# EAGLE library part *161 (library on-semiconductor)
Universal Voltage Monitor Source: www.onsemi.com/pub_link/Collateral/MC34161-D.PDF
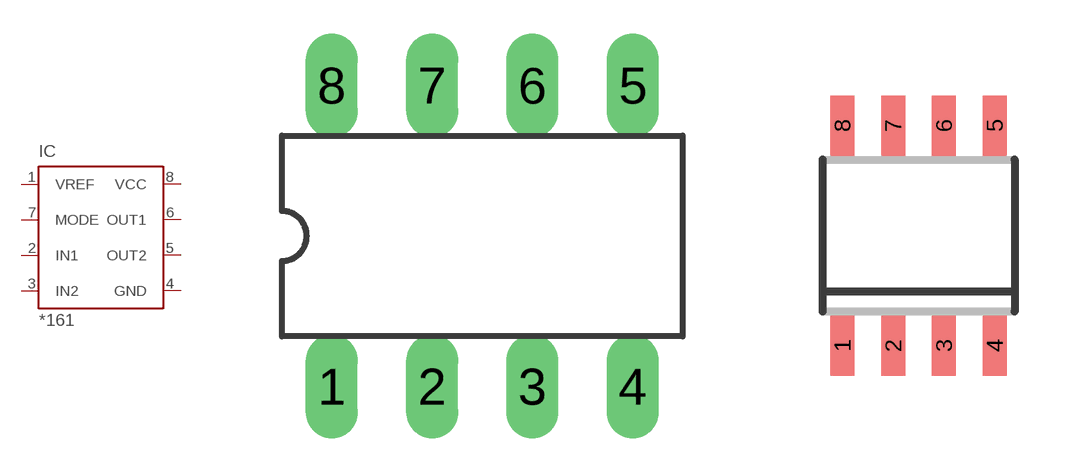
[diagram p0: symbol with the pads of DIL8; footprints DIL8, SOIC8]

Designator prefix IC

## MC33161P (MF: ON SEMICONDUCTOR; MPN: MC33161P; OC_FARNELL: unknown; OC_NEWARK: 07F4769), MC34161P (MF: ON SEMICONDUCTOR; MPN: MC34161P; OC_FARNELL: unknown; OC_NEWARK: 07F5035)  [DIL8]
1  VREF  out
2  IN1  in
3  IN2  in
4  GND  pwr
5  OUT2  oc
6  OUT1  oc
7  MODE  in
8  VCC  pwr

## MC33161D (MF: ON SEMICONDUCTOR; MPN: MC33161D; OC_FARNELL: 1192059; OC_NEWARK: 07F4768), MC34161D (MF: ON SEMICONDUCTOR; MPN: MC34161D; OC_FARNELL: 1652462; OC_NEWARK: 07F5034), NCV33161D (MPN: NCV33161DR2G; OC_FARNELL: unknown; OC_NEWARK: 27M2600)  [SOIC8]
Pads as for DIL8

## MC33161DM (MPN: MC33161DMR2G; OC_FARNELL: 1705447; OC_NEWARK: 04R7825), MC34161DM (MF: ON SEMICONDUCTOR; MPN: MC34161DMR2G; OC_FARNELL: 1652462; OC_NEWARK: 42K0658)  [MICRO8]
Pads as for DIL8

## Footprint DIL8 (pad centres in mm)
Dual In Line package type P
drill 0.813 long: 1 -3.81,-3.81; 2 -1.27,-3.81; 3 1.27,-3.81; 4 3.81,-3.81; 5 3.81,3.81; 6 1.27,3.81; 7 -1.27,3.81; 8 -3.81,3.81

## Footprint SOIC8 (pad centres in mm)
SOIC-8 CASE 751-07 Source: http://www.onsemi.com/pub/Collateral/MC34164-D.PDF D (R-PDSO-G8)PLATIC SMALL-OUTLINE PACKAGE Source: http://focus.ti.com/lit/ds/symlink/tlc27l2.pdf
smd 0.6 x 1.5: 1 -1.905,-2.75; 2 -0.635,-2.75; 3 0.635,-2.75; 4 1.905,-2.75; 5 1.905,2.75; 6 0.635,2.75; 7 -0.635,2.75; 8 -1.905,2.75

## Footprint MICRO8 (pad centres in mm)
Micro8 CASE 846A-02 Source: http://www.onsemi.com/pub/Collateral/MC34164-D.PDF
smd 0.38 x 1.05: 1 -0.975,-2.125; 2 -0.325,-2.125; 3 0.325,-2.125; 4 0.975,-2.125; 5 0.975,2.125; 6 0.325,2.125; 7 -0.325,2.125; 8 -0.975,2.125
